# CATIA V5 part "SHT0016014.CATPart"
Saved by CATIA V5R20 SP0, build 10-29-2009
Part number: SHT0016014
Source: Unknown
Bounding box of the stored display mesh (mm): x -544.085 to 25.758, y -866.5 to -591.5, z 0.9 to 106.4
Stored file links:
  E:\宋国明\项目\02-福田A6-张甲\骨架钣金\2D\宽车主驾底支架\SHT0016014-宽车主驾驶底部支架焊接总成\SHT0016014.CATPart

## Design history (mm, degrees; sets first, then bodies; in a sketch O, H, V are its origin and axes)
Set1
  Point1 to Point4: stored without definition
Body1 "几何体" (main body)
Body2 "SHT0016151-支撑轴套"
  Solid1: solid without history
Body3 "SHT0016151-支撑轴套"
  Solid2: solid without history
Body4 "SHT0016151-支撑轴套"
  Solid3: solid without history
Body5 "SHT0016014.1\\SHT0016145-宽车主驾驶前侧钣金"
  Solid4: solid without history
Body6 "SHT0016014.1\\SHT0016148-宽车主驾驶左侧钣金"
  Solid5: solid without history
Body7 "SHT0016014.1\\SHT0016148-宽车主驾驶左侧钣金"
  Solid6: solid without history
Body8 "SHT0016151-支撑轴套"
  Solid7: solid without history
Body9 "SHT0016014.1\\Q37108-焊接方螺母"
  Solid8: solid without history
Body10 "SHT0016014.1\\Q37108-焊接方螺母"
  Solid9: solid without history
Body11 "SHT0016014.1\\Q37108-焊接方螺母"
  Solid10: solid without history
Body12 "SHT0016014.1\\Q37108-焊接方螺母"
  Solid11: solid without history
Body13 "SHT0016014.1\\Q37108-焊接方螺母"
  Solid12: solid without history
Body14 "SHT0016014.1\\Q37108-焊接方螺母"
  Solid13: solid without history
Body15 "SHT0016014.1\\Q37106-焊接方螺母"
  Solid14: solid without history
Body16 "SHT0016014.1\\Q37110-焊接方螺母"
  Solid15: solid without history
Body17 "SHT0016014.1\\Q37110-焊接方螺母"
  Solid16: solid without history
Body18 "SHT0016014.1\\Q37106-焊接方螺母"
  Solid17: solid without history
Body19 "SHT0016014.1\\Q37106-焊接方螺母"
  Solid18: solid without history
Body20 "SHT0016014.1\\Q37106-焊接方螺母"
  Solid19: solid without history
Body21 "SHT0016014.1\\SHT0016146-宽车主驾驶后侧钣金"
  Solid20: solid without history
  RemoveFace1: RemoveFaces (face of Solid20; face of Solid20; face of Solid20; face of Solid20; face of Solid20; face of Solid20; face of Solid20; face of Solid20)
  Sketch1 on face of Solid20, origin (6.001, -843.9979, 19.9), H (1, 0, 0), V (0, 1, 0)
    point P1 (0, 0)
    reference projected point E1 (0, 0) from Point2
    coincidence: E1 P1
  Hole1: placed by Sketch1, at (6.001, -843.9979, 19.9) direction (0, 0, -1), diameter 12, depth 10
  Sketch2 on face of Solid20, origin (6.0025, -613.9995, 19.9), H (1, 0, 0), V (0, 1, 0)
    point P1 (0, 0)
    reference projected point E1 (0, 0) from Point4
    coincidence: E1 P1
  Hole2: placed by Sketch2, at (6.0025, -613.9995, 19.9) direction (0, 0, -1), diameter 12, depth 10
